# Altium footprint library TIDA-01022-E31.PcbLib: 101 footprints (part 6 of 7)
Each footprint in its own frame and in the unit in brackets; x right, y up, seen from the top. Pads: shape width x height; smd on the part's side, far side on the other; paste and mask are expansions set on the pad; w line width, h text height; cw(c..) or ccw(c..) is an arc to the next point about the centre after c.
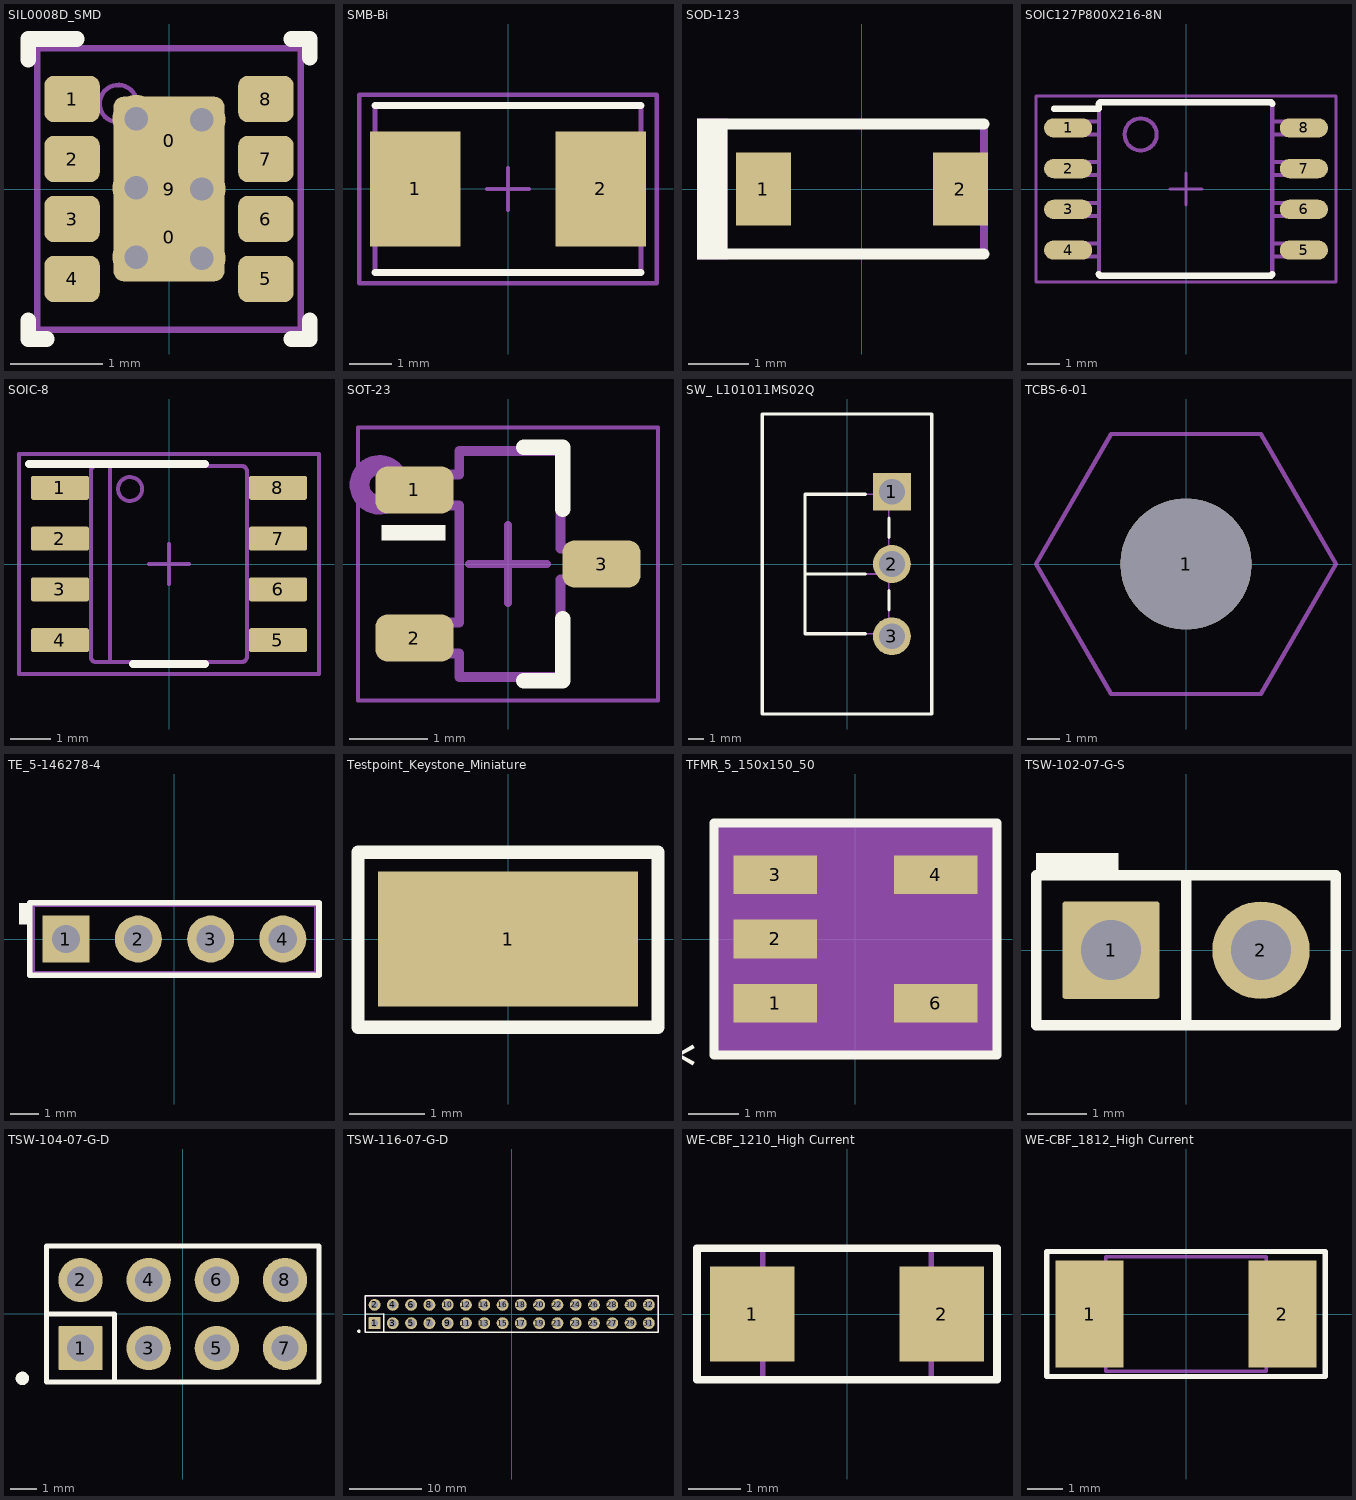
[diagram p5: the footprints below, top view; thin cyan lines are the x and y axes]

## SIL0008D_SMD [mm] "SIP, 8-Leads, Body 2.8x3.0mm, Pitch 0.65mm, Thermal Pad 1.9x1.1mm"
height 1.53
pads (11):
  rrect50% 1.04x0.85 on Top Paste: 0(0,-0.525) 0(0,0.525)
  rrect40% 0.6x0.5 smd paste-0.05 mask-0.05: 1(-1.05,0.975) 2(-1.05,0.325) 3(-1.05,-0.325) 4(-1.05,-0.975) 5(1.05,-0.975) 6(1.05,-0.325) 7(1.05,0.325) 8(1.05,0.975)
  rrect17% 1.2x2 smd paste-0.6 mask-0.05: 9(0,0)
via 0.356,-0.75 diameter 0.508 hole 0.254
via 0.356,0.75 diameter 0.508 hole 0.254
via 0.356,0 diameter 0.508 hole 0.254
via -0.356,0.012 diameter 0.508 hole 0.254
via -0.356,0.762 diameter 0.508 hole 0.254
via -0.356,-0.738 diameter 0.508 hole 0.254
Top Overlay:
  lines w0.17: -1.525,-1.425 -1.525,-1.625 -1.325,-1.625 ; -1.525,1.4 -1.525,1.625 -1,1.625 ; 1.325,-1.625 1.525,-1.625 1.525,-1.425 ; 1.325,1.625 1.525,1.625 1.525,1.425
Mechanical 5:
  circle w0.05: c-0.55,0.925 r0.202
  lines w0.07: -1.425,-1.525 -1.425,1.525 1.425,1.525 1.425,-1.525 -1.425,-1.525
  text ".Designator" at -0.638,-0.325 h0.51
3D body: height 1.53, standoff 1.53, extent -0.751,0.724 -0.349,1.126
3D body "SIL0008D.stp": height 1.53, standoff 0, extent -1.4,-1.5 1.4,1.5

## SMB-Bi [mm] "Molded Diode, 2-Leads, Body 5.4x3.6mm, IPC Medium Density, based on OnSemi component dimensions"
height 2.65
pads (2):
  rect 2.159x2.743 smd: 1(-2.21,0) 2(2.21,0)
Top Overlay:
  lines w0.178: -3.175,-1.994 3.175,-1.994 ; -3.175,1.994 3.175,1.994
Mechanical 5:
  lines w0.127: -3.175,-1.994 3.175,-1.994 3.175,-1.765 3.175,1.765 3.175,1.994 -3.175,1.994 -3.175,1.765 -3.175,-1.765 -3.175,-1.994
  text ".Designator" at 0.201,-0.823 h0.51
Mechanical 15:
  lines w0.1: -0.5,0 0.5,0 ; 0,-0.5 0,0.5 ; -3.55,-2.25 -3.55,2.25 3.55,2.25 3.55,-2.25 -3.55,-2.25
3D body "SMB-Bi.stp": height 2.26, standoff 0.01, extent -2.65,-1.85 2.65,1.85

## SOD-123 [mm] "On Semi recommended land pattern"
height 1.35
pads (2):
  rect 0.915x1.22 smd: 1(-1.637,0) 2(1.637,0)
Top Overlay:
  rectangle: -2.741,-1.168 -2.233,1.168
  lines w0.178: -2.413,-1.079 2.032,-1.079 ; -2.413,1.079 2.032,1.079
Mechanical 5:
  rectangle: -2.741,-1.168 -2.233,1.168
  lines w0.127: -2.413,-1.079 2.032,-1.079 2.032,1.079 -2.413,1.079
  text ".Designator" at -0.77,0.556 h0.51
3D body "SOD-123.stp": height 1.35, standoff 0, extent -1.932,-0.9 1.932,0.9

## SOIC127P800X216-8N [mm] "SOIC, 8-Leads, Body 5.3x5.3mm (max), Pitch 1.27mm, IPC Medium Density"
height 2.159
pads (8):
  oval 1.5x0.6 smd: 1(-3.675,1.905) 2(-3.675,0.635) 3(-3.675,-0.635) 4(-3.675,-1.905) 5(3.675,-1.905) 6(3.675,-0.635) 7(3.675,0.635) 8(3.675,1.905)
Top Overlay:
  lines w0.2: -4.113,2.505 -3.713,2.505 -3.573,2.505 -3.289,2.505 -2.963,2.505 -2.713,2.505 -2.713,2.65 cw(c-2.663,2.65) -2.663,2.7 -2.6,2.7 -2.159,2.7 2.508,2.7 2.637,2.7 cw(c2.637,2.65) 2.687,2.65 ; -2.713,-2.65 ccw(c-2.663,-2.65) -2.663,-2.7 -2.6,-2.7 -2.159,-2.7 2.508,-2.7 2.637,-2.7 ccw(c2.637,-2.65) 2.687,-2.65
Mechanical 5:
  lines w0.127: -2.713,-2.105 -2.963,-2.105 -3.289,-2.105 -3.573,-2.105 -3.713,-2.105 -4.113,-2.105 -4.113,-1.705 -3.713,-1.705 -3.573,-1.705 -3.289,-1.705 -2.963,-1.705 -2.713,-1.705 ; -2.713,-0.835 -2.963,-0.835 -3.289,-0.835 -3.573,-0.835 -3.713,-0.835 -4.113,-0.835 -4.113,-0.435 -3.713,-0.435 -3.573,-0.435 -3.289,-0.435 -2.963,-0.435 -2.713,-0.435 ; -2.713,0.435 -2.963,0.435 -3.289,0.435 -3.573,0.435 -3.713,0.435 -4.113,0.435 -4.113,0.835 -3.713,0.835 -3.573,0.835 -3.289,0.835 -2.963,0.835 -2.713,0.835 ; -2.713,1.705 -2.963,1.705 -3.289,1.705 -3.573,1.705 -3.713,1.705 -4.113,1.705 -4.113,2.105 -3.713,2.105 -3.573,2.105 -3.289,2.105 -2.963,2.105 -2.713,2.105 ; 2.687,-2.105 2.937,-2.105 3.263,-2.105 3.547,-2.105 3.687,-2.105 4.087,-2.105 4.087,-1.705 3.687,-1.705 3.547,-1.705 3.263,-1.705 2.937,-1.705 2.687,-1.705 ; 2.687,-0.835 2.937,-0.835 3.263,-0.835 3.547,-0.835 3.687,-0.835 4.087,-0.835 4.087,-0.435 3.687,-0.435 3.547,-0.435 3.263,-0.435 2.937,-0.435 2.687,-0.435 ; 2.687,0.435 2.937,0.435 3.263,0.435 3.547,0.435 3.687,0.435 4.087,0.435 4.087,0.835 3.687,0.835 3.547,0.835 3.263,0.835 2.937,0.835 2.687,0.835 ; 2.687,1.705 2.937,1.705 3.263,1.705 3.547,1.705 3.687,1.705 4.087,1.705 4.087,2.105 3.687,2.105 3.547,2.105 3.263,2.105 2.937,2.105 2.687,2.105 ; -2.713,-2.65 ccw(c-2.663,-2.65) -2.663,-2.7 -2.6,-2.7 -2.159,-2.7 2.508,-2.7 2.637,-2.7 ccw(c2.637,-2.65) 2.687,-2.65 2.687,2.65 ccw(c2.637,2.65) 2.637,2.7 2.508,2.7 -2.159,2.7 -2.6,2.7 -2.663,2.7 ccw(c-2.663,2.65) -2.713,2.65 -2.713,-2.65 ; -1.913,1.7 cw(c-1.413,1.7) -0.913,1.7 cw(c-1.413,1.7) -1.913,1.7
  text ".Designator" at 0.369,-0.785 h0.51
Mechanical 15:
  lines w0.1: -0.5,0 0.5,0 ; 0,-0.5 0,0.5 ; -4.675,-2.9 4.675,-2.9 4.675,2.9 -4.675,2.9 -4.675,-2.9
3D body "SOIC-8-208.stp": height 2.17, standoff 0.02, extent -4.1,-2.7 4.1,2.7

## SOIC-8 [mm] "duplicate of SO-8.  SOIC, 8-Leads, Body 5.0x4.0mm (max), Pitch 1.27mm, IPC Medium Density"
height 1.75
pads (8):
  rrect17% 1.45x0.6 smd: 1(-2.725,1.905) 2(-2.725,0.635) 3(-2.725,-0.635) 4(-2.725,-1.905) 5(2.725,-1.905) 6(2.725,-0.635) 7(2.725,0.635) 8(2.725,1.905)
Top Overlay:
  lines w0.2: -3.5,2.5 0.9,2.5 ; -0.9,-2.5 0.9,-2.5
Mechanical 5:
  circle w0.1: c-0.975,1.875 r0.3
  lines w0.1: -1.475,-2.45 -1.475,2.45 ; -2.375,-2.095 -2.375,-1.715 ; -2.375,-2.095 -2.589,-2.095 -3.002,-2.095 -3.002,-1.715 -2.589,-1.715 -2.375,-1.715 ; -2.375,-2.095 -1.995,-2.095 -1.952,-2.095 -1.952,-1.715 -1.995,-1.715 -2.375,-1.715 ; -2.375,-0.825 -2.375,-0.445 ; -2.375,-0.825 -2.589,-0.825 -3.002,-0.825 -3.002,-0.445 -2.589,-0.445 -2.375,-0.445 ; -2.375,-0.825 -1.995,-0.825 -1.952,-0.825 -1.952,-0.445 -1.995,-0.445 -2.375,-0.445 ; -2.375,0.445 -2.375,0.825 ; -2.375,0.445 -2.589,0.445 -3.002,0.445 -3.002,0.825 -2.589,0.825 -2.375,0.825 ; -2.375,0.445 -1.995,0.445 -1.952,0.445 -1.952,0.825 -1.995,0.825 -2.375,0.825 ; -2.375,1.715 -2.375,2.095 ; -2.375,1.715 -2.589,1.715 -3.002,1.715 -3.002,2.095 -2.589,2.095 -2.375,2.095 ; -2.375,1.715 -1.995,1.715 -1.952,1.715 -1.952,2.095 -1.995,2.095 -2.375,2.095 ; -0.332,-2.45 -0.182,-2.45 ; -0.332,-2.45 -0.182,-2.45 ; -0.332,-2.45 -1.825,-2.45 -1.826,-2.45 cw(c-1.825,-2.323) -1.952,-2.324 -1.952,-2.323 -1.952,2.323 -1.952,2.324 cw(c-1.825,2.323) -1.826,2.45 -1.825,2.45 -0.332,2.45 ; -0.332,2.45 -0.182,2.45 ; -0.332,2.45 -0.182,2.45 ; -0.182,-2.45 0.178,-2.45 ; -0.182,2.45 0.178,2.45 ; 0.178,-2.45 0.328,-2.45 ; 0.178,-2.45 0.328,-2.45 ; 0.178,2.45 0.328,2.45 ; 0.178,2.45 0.328,2.45 ; 0.328,-2.45 1.821,-2.45 1.822,-2.45 ccw(c1.821,-2.323) 1.948,-2.324 1.948,-2.323 1.948,2.323 1.948,2.324 ccw(c1.821,2.323) 1.822,2.45 1.821,2.45 0.328,2.45 ; 2.371,-2.095 2.371,-1.715 ; 2.371,-2.095 1.991,-2.095 1.948,-2.095 1.948,-1.715 1.991,-1.715 2.371,-1.715 ; 2.371,-2.095 2.585,-2.095 2.998,-2.095 2.998,-1.715 2.585,-1.715 2.371,-1.715 ; 2.371,-0.825 2.371,-0.445 ; 2.371,-0.825 1.991,-0.825 1.948,-0.825 1.948,-0.445 1.991,-0.445 2.371,-0.445 ; 2.371,-0.825 2.585,-0.825 2.998,-0.825 2.998,-0.445 2.585,-0.445 2.371,-0.445 ; 2.371,0.445 2.371,0.825 ; 2.371,0.445 1.991,0.445 1.948,0.445 1.948,0.825 1.991,0.825 2.371,0.825 ; 2.371,0.445 2.585,0.445 2.998,0.445 2.998,0.825 2.585,0.825 2.371,0.825 ; 2.371,1.715 2.371,2.095 ; 2.371,1.715 1.991,1.715 1.948,1.715 1.948,2.095 1.991,2.095 2.371,2.095 ; 2.371,1.715 2.585,1.715 2.998,1.715 2.998,2.095 2.585,2.095 2.371,2.095
  text ".Designator" at 0.369,-0.624 h0.51
Mechanical 15:
  lines w0.1: -0.5,0 0.5,0 ; 0,-0.5 0,0.5 ; -3.75,-2.75 -3.75,2.75 3.75,2.75 3.75,-2.75 -3.75,-2.75
3D body "SOIC-8akaD0008AakaM08A.stp": height 1.63, standoff 0, extent -3,-2.45 3,2.45

## SOT-23 [mm] "SOT23, 3-Leads, Body 2.9x1.3mm, Pitch 0.95mm, Lead Span 2.5mm, IPC Medium Density"
height 1.1
pads (3):
  rrect50% 1x0.6 smd: 1(-1.2,0.95) 2(-1.2,-0.95) 3(1.2,0)
Top Overlay:
  rectangle: -1.625,0.3 -0.8,0.5
  lines w0.2: 0.2,-1.5 0.7,-1.5 0.7,-0.7 ; 0.2,1.5 0.7,1.5 0.7,0.7
Mechanical 5:
  circle w0.254: c-1.651,1.016 r0.254
  lines w0.127: -1.16,-1.15 -1.16,-0.75 -0.625,-0.75 -0.625,0.75 -1.16,0.75 -1.16,1.15 -0.625,1.15 -0.625,1.45 0.675,1.45 0.675,0.2 1.21,0.2 1.21,-0.2 0.675,-0.2 0.675,-1.45 -0.625,-1.45 -0.625,-1.15 -1.16,-1.15
  text ".Designator" at 0.485,0.269 h0.51
Mechanical 15:
  lines w0.05: -1.925,-1.75 1.925,-1.75 1.925,1.75 -1.925,1.75 -1.925,-1.75
  lines w0.1: -0.5,0 0.5,0 ; 0,-0.5 0,0.5
3D body "SW3dPS-sot-3p290x130ll237h100.STEP": height 1, standoff 0, extent -1.16,-1.45 1.21,1.45

## SW_ L101011MS02Q [mm] "SWITCH SLIDE sPST 4A PCB"
height 14.18
pads (3):
  rect 2.416x2.416 hole 1.65: 1(2.858,4.6)
  round 2.416 hole 1.65: 2(2.857,0) 3(2.858,-4.6)
Top Overlay:
  lines w0.2: -5.405,9.55 5.395,9.55 5.395,-9.55 ; -5.395,9.55 -5.395,-9.55 5.405,-9.55 ; -2.668,-0.635 1.166,-0.635 ; 1.166,-4.445 -2.668,-4.445 -2.668,4.445 1.166,4.445 ; 2.668,-2.911 2.668,-1.689 ; 2.668,1.689 2.668,2.911
Mechanical 5:
  lines w0.1: -2.668,-0.635 -2.668,-4.445 2.668,-4.445 2.668,-0.635 ; -2.668,-0.635 -2.668,4.445 2.668,4.445 2.668,-0.635 ; -2.668,-0.635 2.668,-0.635 ; -5.395,-9.55 -5.395,9.55 5.395,9.55 5.395,-9.55 -5.395,-9.55
  text ".Designator" at 0.533,1.983 h0.51
3D body: height 9.1, standoff 0, extent -5.394,-9.549 5.394,9.549
3D body: height 14.18, standoff 9.1, extent -2.668,-0.635 2.668,4.445

## TCBS-6-01 [mil] "Richco Plastics"
height 375
pads (1):
  round 157 hole 157 unplated mask+10: 1(0,0)
Mechanical 5:
  lines w5: -179.57,0 -89.79,155.51 89.78,155.51 179.56,0 89.78,-155.51 -89.79,-155.51 -179.57,0
  text ".Designator" at -15,9 h20
3D body "Richco_TCBS-6.stp": height 374.61, standoff -387.57, extent -179.57,-155.51 179.56,155.52

## TE_5-146278-4 [mm] "TE CONNECTIVITY"
height 8.128
pads (4):
  rect 1.65x1.65 hole 1: 1(-3.81,0)
  round 1.65 hole 1: 2(-1.27,0) 3(1.27,0) 4(3.81,0)
Top Overlay:
  rectangle: -5.461,0.508 -5.08,1.27
  lines w0.203: -5.08,-1.27 5.08,-1.27 5.08,1.27 -5.08,1.27 -5.08,-1.27
Mechanical 5:
  circle w0.254: c-3.81,0.127 r0.458
  lines w0.102: -4.953,-1.168 -4.953,1.168 4.953,1.168 4.953,-1.168 -4.953,-1.168
  text ".Designator" at -1.778,-0.508 h0.51
3D body: height 2.29, standoff 0, extent -4.952,-1.168 4.952,1.168
3D body: height 8.13, standoff -3.05, extent -4.127,-0.317 -3.492,0.318
3D body: height 8.13, standoff -3.05, extent -1.587,-0.317 -0.952,0.318
3D body: height 8.13, standoff -3.05, extent 0.953,-0.317 1.588,0.318
3D body: height 8.13, standoff -3.05, extent 3.493,-0.317 4.128,0.318

## Testpoint_Keystone_Miniature [mil] "Miniature SMT test point"
height 90.55
pads (1):
  rect 135x70 smd: 1(0,0)
Top Overlay:
  lines w7: -78,-46 78,-46 78,45 5,45 -65,45 -78,45 -78,-38 -78,-46
Mechanical 5:
  lines w5: -78,-46 -78,-38 -78,45 -65,45 5,45 78,45 78,-46 -78,-46
  text ".Designator" at -60,-15 h20
3D body "keystone_5015.stp": height 60.6, standoff 0.6, extent -52.5,-20 52.5,20

## TFMR_5_150x150_50 [mil] "TFMR_5_150X150_50"
height 375.2
pads (5):
  rect 65x30 smd: 1(-62.5,-50) 2(-62.5,0) 3(-62.5,50) 4(62.5,50) 6(62.5,-50)
Top Overlay:
  lines w7: -110,-90 110,-90 110,90 -110,90 -110,-90
  text "*" at -123.2,-61 h42
Mechanical 5:
  lines w1: -75,-75 75,-75 75,75 -75,75 -75,-75
  text "*" at -80,-48.33 h20
Mechanical 16:
  region: 110,-90 -110,-90 -110,90 110,90
Mechanical 27:
  text "2" at -52.5,0 h25
  text "4" at 72.5,50 h25
  text "6" at 72.5,-50 h25
  text "1" at -52.5,-50 h25
  text "3" at -52.5,50 h25

## TSW-102-07-G-S [mm] "Samtec 100mil, 1x2, 230 mil above insulator"
height 8.382
pads (2):
  rrect6% 1.65x1.65 hole 1.016: 1(-1.27,0)
  round 1.65 hole 1.016: 2(1.27,0)
Top Overlay:
  rectangle: -2.54,1.27 -1.143,1.651
  lines w0.178: 0,-1.27 0,1.27 ; -2.54,-1.27 -2.54,1.27 2.54,1.27 2.54,-1.27 -2.54,-1.27
Mechanical 5:
  circle w0.254: c-1.27,0.127 r0.381
  lines w0.127: -2.54,-1.27 2.54,-1.27 2.54,1.27 -2.54,1.27 -2.54,-1.27
  text ".Designator" at -0.126,-0.052 h0.51
3D body "SamtecTSW-07_2x1.stp": height 8.38, standoff -2.54, extent -2.54,-1.27 2.54,1.27

## TSW-104-07-G-D [mm] "Samtec 100mil, 2x4, 230 mil above insulator"
height 8.382
pads (8):
  rrect6% 1.65x1.65 hole 1.016: 1(-3.81,-1.27)
  round 1.65 hole 1.016: 2(-3.81,1.27) 3(-1.27,-1.27) 4(-1.27,1.27) 5(1.27,-1.27) 6(1.27,1.27) 7(3.81,-1.27) 8(3.81,1.27)
Top Overlay:
  circle w0.25: c-5.98,-2.4 r0.125
  lines w0.178: -5.08,0 -2.54,0 -2.54,-2.54 ; -5.08,-2.54 -5.08,2.54 5.08,2.54 5.08,-2.54 -5.08,-2.54
Mechanical 5:
  rectangle: -4.318,-1.778 -3.302,-0.762
  lines w0.127: -5.08,-2.54 5.08,-2.54 5.08,2.54 -5.08,2.54 -5.08,-2.54
  text ".Designator" at -0.199,0.683 h0.51
3D body "SamtecTSW-07_4x2.stp": height 8.38, standoff -2.54, extent -5.08,-2.54 5.08,2.54

## TSW-116-07-G-D [mm] "Samtec 100mil, 2x16, 230 mil above insulator"
height 8.382
pads (32):
  rrect6% 1.65x1.65 hole 1.016: 1(-19.05,-1.27)
  round 1.65 hole 1.016: 2(-19.05,1.27) 3(-16.51,-1.27) 4(-16.51,1.27) 5(-13.97,-1.27) 6(-13.97,1.27) 7(-11.43,-1.27) 8(-11.43,1.27) 9(-8.89,-1.27) 10(-8.89,1.27) 11(-6.35,-1.27) 12(-6.35,1.27) 13(-3.81,-1.27) 14(-3.81,1.27) 15(-1.27,-1.27) 16(-1.27,1.27) 17(1.27,-1.27) 18(1.27,1.27) 19(3.81,-1.27) 20(3.81,1.27) 21(6.35,-1.27) 22(6.35,1.27) 23(8.89,-1.27) 24(8.89,1.27) 25(11.43,-1.27) 26(11.43,1.27) 27(13.97,-1.27) 28(13.97,1.27) 29(16.51,-1.27) 30(16.51,1.27) 31(19.05,-1.27) 32(19.05,1.27)
Top Overlay:
  circle w0.25: c-21.22,-2.4 r0.125
  lines w0.178: -20.32,0 -17.78,0 -17.78,-2.54 ; -20.32,-2.54 -20.32,2.54 20.32,2.54 20.32,-2.54 -20.32,-2.54
Mechanical 5:
  rectangle: -19.558,-1.778 -18.542,-0.762
  lines w0.127: -20.32,-2.54 20.32,-2.54 20.32,2.54 -20.32,2.54 -20.32,-2.54
  text ".Designator" at 0.051,-0.127 h0.51
3D body "SamtecTSW-07_16x2.stp": height 8.38, standoff -2.54, extent -20.32,-2.54 20.32,2.54

## WE-CBF_1210_High Current [mm] "SMD EMI Suppression Ferrite  Bead, body 3.2mmx2.5mm"
height 1.3
pads (2):
  rect 1.6x1.8 smd: 1(-1.8,0) 2(1.8,0)
Top Overlay:
  lines w0.15: -2.85,-1.25 -2.85,1.25 2.85,1.25 2.85,-1.25 -2.85,-1.25
Mechanical 15:
  lines w0.1: -1.6,-1.25 -1.6,1.25 1.6,1.25 1.6,-1.25 -1.6,-1.25
3D body "WE-CBF_1210_CBF.stp": height 1.34, standoff 0.04, extent -1.6,-1.25 1.6,1.25

## WE-CBF_1812_High Current [mm] "SMD EMI Suppression Ferrite  Bead, body 4.5mmx3.2mm"
height 1.5
pads (2):
  rect 1.9x3 smd: 1(-2.7,0) 2(2.7,0)
Top Overlay:
  lines w0.15: -3.9,-1.75 -3.9,1.75 3.9,1.75 3.9,-1.75 -3.9,-1.75
Mechanical 15:
  lines w0.1: -2.25,-1.6 -2.25,1.6 2.25,1.6 2.25,-1.6 -2.25,-1.6
3D body "WE-CBF_1812_CBF.stp": height 1.55, standoff 0.05, extent -2.25,-1.6 2.25,1.6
